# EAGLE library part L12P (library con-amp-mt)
AMP MT CONNECTOR
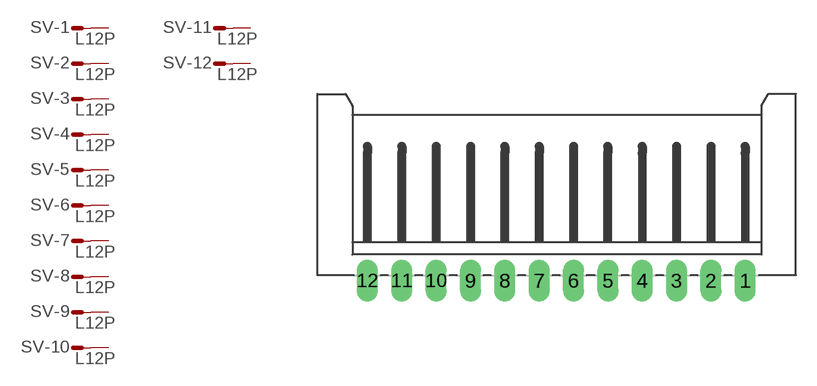
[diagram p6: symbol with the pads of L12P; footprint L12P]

Designator prefix SV; gates -1=M -2=M -3=M -4=M -5=M -6=M -7=M -8=M -9=M -10=M -11=M -12=M

## L12P (OC_FARNELL: unknown; OC_NEWARK: unknown)  [L12P]
1  -1:S  pas
2  -2:S  pas
3  -3:S  pas
4  -4:S  pas
5  -5:S  pas
6  -6:S  pas
7  -7:S  pas
8  -8:S  pas
9  -9:S  pas
10  -10:S  pas
11  -11:S  pas
12  -12:S  pas

## Footprint L12P (pad centres in mm)
AMP MT CONNECTOR
drill 1.016 long: 1 13.75,-6.25; 2 11.25,-6.25; 3 8.75,-6.25; 4 6.25,-6.25; 5 3.75,-6.25; 6 1.25,-6.25; 7 -1.25,-6.25; 8 -3.75,-6.25; 9 -6.25,-6.25; 10 -8.75,-6.25; 11 -11.25,-6.25; 12 -13.75,-6.25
